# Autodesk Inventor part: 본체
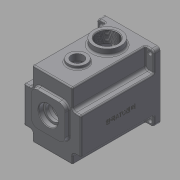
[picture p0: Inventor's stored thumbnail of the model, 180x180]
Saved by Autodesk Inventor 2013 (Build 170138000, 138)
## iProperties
Created: 2016-02
Part Number: 본체
Material: 일반
Document SubType Name: Modeling
Designer: mduedu
Density: 1 g/cm^3
Mass: 499.533 g
Surface Area: 1142.22 cm^2
Volume: 499.533 cm^3
Author: mduedu
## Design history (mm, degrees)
sketch "스케치1"
  geometry: L1 (-47, -47)-(47, -47); L2 (47, -47)-(47, 63); L3 (47, 63)-(-47, 63); L4 (-47, 63)-(-47, -47); 2 further points
  constraints: 8 end point, 2 parallel, 1 horizontal, 1 midpoint, 1 perpendicular, 1 vertical alignment
  dimensions: "d0" = 94 distance of L2.end L3.end; "d155" = 110 distance of L1.end L2.end; "d156" = 47 distance from line of L1 point (0, 0)
extrude "돌출1" new body sketch "스케치1" distance "d2" = 130; taper "d3" = 0 deg
sketch "스케치3"
  geometry: C1 r 40 at (0, 0); 1 further point
  constraints: 1 centre point, 1 coincident
  dimensions: "d9" = 80 diameter of C1
extrude "돌출3" cut sketch "스케치3" distance "d11" = 121; taper "d12" = 0 deg
sketch "스케치4"
  geometry: C1 r 21 at (0, 11); 1 further point
  constraints: 1 centre point, 1 vertical alignment
  dimensions: "d13" = 21 radius of C1; "d15" = 11 distance of point (0, 0) C1.centre
extrude "돌출4" join sketch "스케치4" distance "d16" = 7; taper "d17" = 0 deg
sketch "스케치5"
  geometry: C1 r 15 at (0, -20); 1 further point
  constraints: 1 centre point, 1 vertical alignment
  dimensions: "d18" = 15 radius of C1; "d20" = 20 distance of point (0, 0) C1.centre
extrude "돌출5" join sketch "스케치5" distance "d21" = 7; taper "d22" = 0 deg
sketch "스케치6"
  geometry: L1 (-28, -17)-(28, -17); L2 (28, -17)-(28, 39); L3 (28, 39)-(-28, 39); L4 (-28, 39)-(-28, -17); L5 (-28, -17)-(28, 39); L6 (28, -17)-(-28, 39); C1 r 28 at (0, 11); A1 r 21 centre (0, 11) between (8.978, -7.984) and (-8.978, -7.984) reference; 1 further point
  constraints: 12 end point, 2 midpoint, 2 parallel, 2 tangent, 1 centre point, 1 coincident, 1 horizontal, 1 perpendicular
  dimensions: "d23" = 56 diameter of C1
extrude "돌출6" join sketch "스케치6" distance "d25" = 7; taper "d26" = -3 deg
hole "구멍1" diameter "d29" = 35; stored, may be unused: countersink angle "d33" = 90 deg, drill point angle "d35" = 0 deg; dims "d27" = 10, "d28" = 10, "d30" = 6, "d31" = 4, "d32" = 2, "d34" = 10
hole "구멍2" diameter "d38" = 22; stored, may be unused: countersink angle "d42" = 90 deg, drill point angle "d44" = 0 deg; dims "d36" = 10, "d37" = 10, "d39" = 6, "d40" = 4, "d41" = 2, "d43" = 7
hole "구멍3" diameter "d47" = 19; stored, may be unused: countersink angle "d51" = 90 deg, drill point angle "d53" = 0 deg; dims "d45" = 10, "d46" = 10, "d48" = 6, "d49" = 4, "d50" = 2, "d52" = 1
hole "구멍4" diameter "d56" = 32; stored, may be unused: countersink angle "d60" = 90 deg, drill point angle "d62" = 0 deg; dims "d57" = 6, "d58" = 4, "d59" = 2, "d61" = 8, "d220" = 10, "d221" = 10
hole "구멍5" diameter "d65" = 25; stored, may be unused: countersink angle "d69" = 90 deg, drill point angle "d71" = 0 deg; dims "d63" = 10, "d64" = 10, "d66" = 6, "d67" = 4, "d68" = 2, "d70" = 8
fillet "모깎기2" dims "d73" = 0.3
fillet "모깎기3" dims "d74" = 2
chamfer "모따기1" distance "d75" = 1; stored, may be unused: second distance "d76" = 2, angle "d77" = 45 deg
fillet "모깎기4" dims "d78" = 3
sketch "스케치16"
  geometry: L1 (-23, 32.726)-(23, 32.726); L2 (23, 32.726)-(23, 53); L3 (23, 53)-(-23, 53); L4 (-23, 53)-(-23, 32.726); L5 (-47, 63)-(47, 63) reference; 3 further points
  constraints: 8 end point, 2 parallel, 1 horizontal, 1 midpoint, 1 perpendicular, 1 vertical alignment, 2 other
  dimensions: "d160" = 46 distance of L2.end L3.end; "d163" = 10 distance between parallel lines of L3 L5
extrude "돌출15" cut sketch "스케치16" stored distance "d164" = 10; taper "d165" = 0 deg
fillet "모깎기5" dims "d79" = 2
fillet "모깎기15" dims "d166" = 5
sketch "스케치7"
  geometry: L1 (-23, 48)-(-23, 35.228) reference; L2 (23, 35.228)-(23, 48) reference; L3 (18, 53)-(-18, 53) reference; L4 (47, 63)-(47, -47) reference; L5 (47, -47)-(-47, -47) reference; L6 (-47, -47)-(-47, 63) reference; L7 (-47, 63)-(47, 63) reference; L8 (-26, 48)-(-26, 35.228); L9 (26, 35.228)-(26, 48); L10 (18, 56)-(-18, 56); C1 r 43 at (0, 0); A1 r 5 centre (-18, 48) between (-18, 53) and (-23, 48) reference; A2 r 5 centre (-28, 35.228) between (-24.889, 31.314) and (-23, 35.228) reference; A3 r 40 centre (0, 0) between (-24.889, 31.314) and (24.889, 31.314) reference; A4 r 5 centre (28, 35.228) between (23, 35.228) and (24.889, 31.314) reference; A5 r 5 centre (18, 48) between (23, 48) and (18, 53) reference; A6 r 8 centre (-18, 48) between (-18, 56) and (-26, 48); A7 r 2 centre (-28, 35.228) between (-26.756, 33.662) and (-26, 35.228); A8 r 43 centre (0, 0) between (-26.756, 33.662) and (26.756, 33.662); A9 r 2 centre (28, 35.228) between (26, 35.228) and (26.756, 33.662); A10 r 8 centre (18, 48) between (26, 48) and (18, 56); 1 further point
  constraints: 10 point on circle, 6 centre point, 6 end point, 1 coincident, 7 other
  dimensions: "d80" = 86 diameter of C1; "d167" = 3 distance between parallel lines of L3 L10
extrude "돌출7" cut sketch "스케치7" distance "d83" = 9; taper "d84" = 0 deg
sketch "스케치8" dims "d168" = 36
  geometry: L1 (-36, 4)-(-39.799, 4); L2 (-36, -4)-(-39.799, -4); A1 r 4 centre (-36, 0) between (-36, 4) and (-36, -4); A2 r 40 centre (0, 0) between (-24.889, 31.314) and (24.889, 31.314) reference; A3 r 40 centre (0, 0) between (-39.799, 4) and (-39.799, -4); 2 further points
  constraints: 5 point on circle, 4 end point, 2 centre point, 2 coincident, 2 horizontal alignment, 2 tangent, 1 horizontal, 1 parallel, 2 other
  dimensions: "d169" = 4 radius of A1
extrude "돌출9" join sketch "스케치8" stored distance "d89" = 9; taper "d90" = 0 deg
fillet "모깎기6" dims "d91" = 3.5
node "작업 평면1"
sketch "스케치9"
  geometry: L1 (47, 63)-(33, 63); L2 (33, 63)-(33, 30); L3 (33, 30)-(47, 30); L4 (47, 30)-(47, 63); L5 (47, 63)-(-47, 63) reference; L6 (47, -47)-(47, 63) reference; A1 r 40 centre (0, 0) between (-39.148, -8.214) and (39.148, -8.214) reference; 1 further point
  constraints: 8 end point, 2 parallel, 1 coincident, 1 horizontal, 1 perpendicular
  dimensions: "d95" = 33 distance from line of L2 point (0, 0); "d96" = 30 distance from line of L3 point (0, 0)
extrude "돌출10" cut sketch "스케치9" distance "d97" = 110; taper "d98" = 0 deg
extrude "돌출21" cut sketch "스케치9" stored distance "d217" = 10; taper "d218" = 0 deg
sketch "스케치11" dims "d20" = 20
  geometry: L1 (-40, -40)-(40, -40); L2 (40, -40)-(40, 56); L3 (40, 56)-(-40, 56); L4 (-40, 56)-(-40, -40); L5 (-47, -47)-(47, -47) reference; L6 (47, 63)-(-47, 63) reference; L7 (-47, 63)-(-47, -47) reference; C1 r 3.5 at (-40, 56); C2 r 3.5 at (40, 56); C3 r 3.5 at (40, -40); C4 r 3.5 at (-40, -40); 1 further point
  constraints: 8 end point, 4 centre point, 4 coincident, 3 equal radius, 2 parallel, 1 horizontal, 1 perpendicular
  dimensions: "d109" = 80 distance of L2.end L3.end; "d112" = 7 diameter of C1; "d157" = 7 distance from line of L1.start L5; "d158" = 7 distance between parallel lines of L6 L3; "d159" = 7 distance from line of L7 L3.end
extrude "돌출12" cut sketch "스케치11" stored distance "d113" = 63; taper "d114" = 0 deg
fillet "모깎기7" dims "d115" = 5, "d187" = 5
fillet "모깎기8" dims "d116" = 5
fillet "모깎기18" dims "d219" = 2
fillet "모깎기12" dims "d120" = 2
fillet "모깎기13" dims "d121" = 2
sketch "스케치12"
  geometry: 3 further points
  constraints: 2 horizontal alignment
hole "구멍6" sketch "스케치12" at (36, 0), (-36, 0) diameter "d122" = 3.242; stored, may be unused: countersink angle "d126" = 90 deg, drill point angle "d128" = 120 deg; dims "d123" = 7, "d124" = 4, "d125" = 2, "d127" = 9
fillet "모깎기14" dims "d147" = 10
chamfer "모따기4" distance "d151" = 1; stored, may be unused: second distance "d152" = 2, angle "d153" = 45 deg
sketch "스케치20"
  geometry: L1 (73, -12)-(73, -130) reference; L2 (84, -8)-(77, -8) reference; L3 (84, 0)-(84, -8) reference; L4 (84, 0)-(0, 0) reference; L5 (7, -8)-(0, -8) reference; L6 (11, -130)-(11, -12) reference; L7 (0, -8)-(0, 0) reference; L8 (73, -130)-(11, -130) reference; L9 (42, 0)-(42, -130); C1 r 10 at (42, -89); A1 r 4 centre (77, -12) between (77, -8) and (73, -12) reference; A2 r 4 centre (7, -12) between (11, -12) and (7, -8) reference
  constraints: 2 end point, 1 centre point, 1 midpoint, 1 point on line
  dimensions: "d189" = 20 diameter of C1; "d190" = 41 distance from line of C1.centre L8
extrude "돌출19" cut sketch "스케치20" stored distance "d191" = 10; taper "d192" = 0 deg
sketch "스케치18"
  geometry: C1 r 15 at (42, -89); C2 r 10 at (42, -89) reference; 1 further point
  constraints: 1 centre point, 1 concentric
  dimensions: "d174" = 30 diameter of C1
extrude "돌출17" join sketch "스케치18" distance "d175" = 5; taper "d176" = 0 deg
fillet "모깎기16" dims "d177" = 2
sketch "스케치19"
  geometry: C1 r 10 at (18, 80) reference; C2 r 15 at (18, 80); 1 further point
  constraints: 1 centre point, 1 coincident
  dimensions: "d178" = 30 diameter of C2
extrude "돌출18" cut sketch "스케치19" distance "d181" = 5; taper "d182" = 0 deg
chamfer "모따기5" distance "d183" = 0.5; stored, may be unused: second distance "d184" = 2, angle "d185" = 45 deg
sketch "스케치21"
  geometry: L1 (-12, 14)-(-130, 14) reference; L2 (-8, 0)-(-8, 10) reference; L3 (0, 0)-(0, 100) reference; L4 (-8, 100)-(0, 100) reference; L5 (-8, 74)-(-8, 100) reference; L6 (-130, 70)-(-12, 70) reference; L7 (-130, 14)-(-130, 70) reference; L8 (0, 0)-(-8, 0) reference; L9 (-130, 14)-(-130, 70) reference; L10 (27.4, 42)-(-164.4, 42) reference; A1 r 4 centre (-12, 74) between (-12, 70) and (-8, 74) reference; A2 r 4 centre (-12, 10) between (-8, 10) and (-12, 14) reference; 3 further points
  constraints: 1 coincident, 1 point on line, 1 other
  dimensions: "d222" = 65 distance from line of point (-65, 42) L9
feature "엠보싱2" sketch "스케치21" dims "d20" = 20, "d193" = 0.5, "d194" = 0
sketch "스케치22"
  geometry: L1 (73, -12)-(73, -130) reference; L2 (84, -8)-(77, -8) reference; L3 (84, 0)-(84, -8) reference; L4 (84, 0)-(0, 0) reference; L5 (7, -8)-(0, -8) reference; L6 (11, -130)-(11, -12) reference; L7 (0, -8)-(0, 0) reference; L8 (73, -130)-(11, -130) reference; L9 (42, -130)-(42, 0); C1 r 17 at (42, -89) reference; C2 r 22.5 at (42, -40); A1 r 4 centre (77, -12) between (77, -8) and (73, -12) reference; A2 r 4 centre (7, -12) between (11, -12) and (7, -8) reference
  constraints: 2 end point, 1 centre point, 1 midpoint, 1 point on line
  dimensions: "d195" = 45 diameter of C2; "d197" = 40 distance from line of C2.centre L4
extrude "돌출20" join sketch "스케치22" distance "d198" = 10; taper "d199" = 0 deg
fillet "모깎기17" dims "d200" = 3
hole "구멍7" diameter "d203" = 33.376; stored, may be unused: countersink angle "d207" = 90 deg, drill point angle "d209" = 118 deg; dims "d204" = 6, "d205" = 4, "d206" = 2, "d208" = 8, "d223" = 10, "d224" = 10
chamfer "모따기6" distance "d210" = 1; stored, may be unused: second distance "d211" = 2, angle "d212" = 45 deg
fillet "모깎기19" dims "d225" = 2
node "솔리드1"
pattern_circular "원형 패턴1" dims angle "d93" = 360 deg
mirror "대칭1"
mirror "대칭2"
node "투영된 루프1"
node "투영된 루프2"
node "투영된 루프3"
node "절단 모서리 투영3"
